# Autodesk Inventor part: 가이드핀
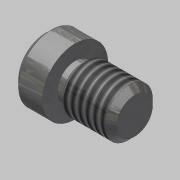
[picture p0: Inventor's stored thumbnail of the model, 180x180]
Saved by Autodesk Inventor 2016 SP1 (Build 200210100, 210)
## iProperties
Created: 2019-02
Part Number: 가이드핀
Material: 스테인리스강
Document SubType Name: Modeling
Designer: mduedu
Density: 1 g/cm^3
Appearance: 반광택
Author: mduedu
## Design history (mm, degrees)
sketch "스케치1"
  geometry: C1 r 5.5 at (0, 0); 1 further point
  constraints: 1 centre point, 1 coincident
  dimensions: "d0" = 11 diameter of C1
extrude "돌출1" new body sketch "스케치1" distance "d1" = 5; taper "d2" = 0 deg
sketch "스케치2"
  geometry: C1 r 3 at (0, 0); 1 further point
  constraints: 1 centre point, 1 coincident
  dimensions: "d3" = 6 diameter of C1
extrude "돌출2" join sketch "스케치2" distance "d4" = 1; taper "d5" = 0 deg
sketch "스케치3"
  geometry: C1 r 4 at (0, 0); 1 further point
  constraints: 1 centre point, 1 coincident
  dimensions: "d6" = 8 diameter of C1
extrude "돌출3" join sketch "스케치3" distance "d7" = 9; taper "d8" = 0 deg
chamfer "모따기1" distance "d9" = 1; stored, may be unused: second distance "d10" = 2, angle "d11" = 45 deg
feature "스레드1" dims "d12" = 10, "d13" = 0
node "솔리드1"
